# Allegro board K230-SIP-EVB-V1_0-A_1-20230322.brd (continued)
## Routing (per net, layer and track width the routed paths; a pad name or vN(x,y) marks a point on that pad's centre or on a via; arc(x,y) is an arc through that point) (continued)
QSPI0_CS0: length 42
  TOP w0.076: U19.E2 33.69,84.24 34.01,84.56 34.29,84.56 34.49,84.76 34.49,85.09
  TOP w0.127: 34.49,85.09 34.49,86.66 35.62,87.79 35.62,89.73 36.32,90.42 36.32,91.95 35.69,92.58 35.69,96.27 37.08,97.66 37.08,101.73 39.88,104.52 43.43,104.52 44.07,105.16 44.07,109.6 43.81,109.86 38.35,109.86 v1(37.72,110.49) U37.1
  BOTTOM w0.127: R212.2 v1(37.72,110.49)
QSPI0_D0: length 28.4
  TOP w0.076: 33.84,85.09 33.84,84.77 33.66,84.58 33.4,84.58 33.05,84.24 U19.F2
  TOP w0.127: U37.5 41.66,106.68 41.53,106.55 41.53,105.16 41.27,104.9 39.62,104.9 36.74,102.02 36.74,97.72 35.03,96 35.03,87.96 33.84,86.78 33.84,85.09
QSPI0_D1: length 29
  TOP w0.127: U19.F1 32.87,87.18 33.68,87.99 33.68,96.53 35.43,98.29 35.43,103.12 38.48,106.17 38.48,109.09 38.35,109.22 U37.2
QSPI0_D2: length 28.8
  TOP w0.127: U19.G1 32.22,88.08 33.06,88.93 33.06,97.07 34.04,98.04 34.04,99.11 34.37,99.44 34.37,102.69 36.35,104.68 36.35,104.89 35.93,105.31 35.93,105.52 36.07,105.67 36.28,105.67 36.71,105.25 36.92,105.25 37.97,106.3 37.97,107.82 37.85,107.95 U37.3
QSPI0_D3: length 30.3
  TOP w0.076: U19.G2 32.42,84.24 32.75,84.57 33.05,84.57 33.19,84.71 33.19,85.09
  TOP w0.127: U37.7 41.53,109.22 41.27,108.97 41.27,108.46 35.71,102.9 35.71,98.16 34,96.44 34,87.85 33.19,87.05 33.19,85.09
RMICN: length 65.3
  TOP w0.076: 36.25,83.91 35.79,83.91 U19.B3
  TOP w0.127: v1(59.82,117.73) 59.82,117.22 54.56,111.96 54.56,104.22 48.85,98.51 44.15,98.51 41.57,95.92 41.57,93.43 39.48,91.34 39.48,88.27 37.1,85.88 37.1,84.57 36.44,83.91 36.25,83.91 ; C285.1 v1(67.31,131.57)
  ART03 w0.127: v1(59.82,117.73) 60.33,118.24 60.33,119.51 67.31,126.49 v1(67.31,131.57)
RMICP: length 65.4
  TOP w0.127: C287.1 68.58,131.7 v1(68.45,131.57) ; v1(60.96,117.73) 54.86,111.63 54.86,104.01 49,98.15 44.3,98.15 41.91,95.76 41.91,93.36 39.76,91.21 39.76,88.14 37.35,85.74 37.35,84.42 36.52,83.59 U19.A3
  ART03 w0.127: v1(68.45,131.57) 68.45,125.22 v1(60.96,117.73)
RTC_1V8: length 139.7
  TOP w0.254: U19.D11 v3(34.49,78.06) U19.D12
  TOP w0.381: v1(76.2,64.01) 76.2,77.47 74.38,79.29 57.95,79.29 v1(57.02,78.36) 57.02,76.45 56.64,76.07 Y4.4 ; 70.87,38.1 70.87,35.94 71.36,35.44 72.52,35.44
  ART03 w0.381: v3(34.49,78.06) 48.94,78.06 49.4,77.6 50.08,77.6 50.55,78.06 56.72,78.06 v1(57.02,78.36) ; v1(76.2,64.01) 78.11,62.1 78.11,44.7 74.93,41.53 v1(74.93,40.13)
  ART03 w0.508: 57.78,1.91 60.33,1.91 61.59,3.17 64.14,3.17 65.41,1.91 66.67,3.17 66.67,19.43 73.79,26.54
  BOTTOM w0.305: v3(34.49,78.06) 34.54,78.11 C229.1 C230.1
  BOTTOM w0.381: R202.2 57.78,7.87 56.52,6.6 56.52,3.17 57.78,1.91
  vias: v1(74.93,38.86)
RTC_CLK_IN: length 16.6
  TOP w0.076: 34.49,74.93 34.49,75.46 U19.D15
  TOP w0.127: 34.49,74.93 34.49,74.73 36.2,73.03 48.51,73.03 R107.2
RTC_CLK_OUT: length 16.3
  TOP w0.127: U19.D16 34.17,74.54 36.2,72.52 R106.1
RTC_INT0: length 102.7
  TOP w0.127: U19.C16 34.82,74.8 35.96,73.66 46.48,73.66 v1(47.62,74.8)
  ART03 w0.127: v1(47.62,74.8) 48.77,73.66 58.29,73.66 58.93,74.3 64.48,74.3 68.83,69.94 68.83,64.64 72.14,61.34 72.14,57.53 72.64,57.02 72.64,55.5 71.88,54.74 71.88,44.2 71.25,43.56 71.25,27.18 v1(67.44,23.37)
  BOTTOM w0.127: 66.67,10.03 67.06,10.41 TVS8.1 67.94,22.86 v1(67.44,23.37)
RTC_INT1: length 102.5
  TOP w0.127: U19.D14 v3(34.49,76.11)
  ART03 w0.127: v3(34.49,76.11) 34.49,75.62 36.83,73.28 58.55,73.28 59.23,73.96 64.34,73.96 66.8,71.5 66.8,65.66 71.5,60.96 71.5,44.45 70.81,43.76 70.81,28.01 v1(66.17,23.37)
  BOTTOM w0.127: 64.14,10.03 64.52,10.41 TVS9.1 65.41,22.61 v1(66.17,23.37)
RTC_INT2: length 173.3
  TOP w0.127: v1(63.5,10.79) 63.5,9.4 60.07,5.97 44.07,5.97 41.78,8.26 6.35,8.26 4.06,10.54 4.06,13.72 J32.4 ; U19.E14 v3(33.84,76.11)
  ART03 w0.127: v3(33.84,76.11) 34.19,75.76 34.19,75.41 36.7,72.9 58.67,72.9 59.46,73.69 64.21,73.69 66.42,71.48 66.42,64.52 68.9,62.04 68.9,60.01 71.12,57.78 71.12,44.58 70.48,43.94 70.48,28.83 63.5,21.84 v1(63.5,10.79)
  BOTTOM w0.127: 61.59,10.03 61.98,10.41 TVS10.1 63.25,10.79 v1(63.5,10.79)
RTC_INT4: length 158.6
  TOP w0.127: U19.F14 v3(33.19,76.11) ; v1(60.96,10.79) 60.96,7.75 59.69,6.48 44.2,6.48 42.04,8.64 13.59,8.64 J33.2
  ART03 w0.102: 33.52,75.07 33.52,75.79 v3(33.19,76.11)
  ART03 w0.127: v1(60.96,10.79) 63.12,12.95 63.12,21.97 70.1,28.96 70.1,44.07 70.74,44.7 70.74,57.66 68.58,59.82 68.58,61.85 66.04,64.39 66.04,71.37 64.01,73.41 59.69,73.41 58.8,72.52 35.8,72.52 33.52,74.8 33.52,75.07
  BOTTOM w0.127: v1(60.96,10.79) 60.71,10.79 TVS11.1 59.44,10.41 59.05,10.03
RTC_OUT0: length 117
  TOP w0.127: U19.F13 v3(33.19,76.76)
  ART03 w0.102: 35.62,77.09 33.52,77.09 v3(33.19,76.76)
  ART03 w0.127: 35.62,77.09 35.87,76.83 48.13,76.83 49,75.97 62.13,75.97 62.61,76.45 63.96,76.45 70.23,70.18 70.23,65.53 73.79,61.98 73.79,59.94 74.3,59.44 74.3,49.4 73.66,48.77 73.66,42.04 72.64,41.02 72.64,27.3 66.67,21.34 v1(64.9,21.34)
  BOTTOM w0.127: 55.24,10.03 55.63,10.41 TVS12.1 ; 57.78,10.03 57.4,10.41 TVS12.1 ; TVS12.1 56.52,10.92 56.9,11.3 62.61,11.3 64.14,12.83 64.14,20.57 v1(64.9,21.34)
RTC_OUT1: length 61
  TOP w0.127: U19.E13 v3(33.84,76.76)
  ART03 w0.102: 34.82,75.93 34.82,76.31 34.69,76.44 34.17,76.44 v3(33.84,76.76)
  ART03 w0.127: 34.82,75.93 35.43,75.31 47.88,75.31 48.9,74.3 56.26,74.3 56.64,74.68 64.52,74.68 69.13,70.07 69.13,64.86 72.64,61.34 72.64,57.66 73.15,57.15 73.15,53.98 73.66,53.47 v1(73.66,51.44)
  BOTTOM w0.127: R92.1 v1(73.66,51.44)
SD2_CLK: length 61.3
  TOP w0.127: U19.P11 v3(27.99,78.06)
  ART03 w0.127: v1(25.05,97.28) 26.92,95.41 26.92,91.85 26.78,91.7 26.44,91.7 26.29,91.55 26.29,91.34 26.44,91.2 26.78,91.2 26.92,91.05 26.92,90.84 26.78,90.69 26.44,90.69 26.29,90.54 26.29,90.33 26.44,90.18 26.78,90.18 26.92,90.03 26.92,89.82 26.78,89.67 26.44,89.67 26.29,89.52 26.29,89.31 26.44,89.16 26.78,89.16 26.92,89.01 26.92,87.76 25.65,86.49 25.65,79.76 27.35,78.06 v3(27.99,78.06)
  BOTTOM w0.127: v1(25.05,97.28) 21.44,97.28 17.4,101.33 17.4,114.43 14.99,116.84 14.99,118.36 14.73,118.62 R156.2 U24.3 14.86,120.97 14.99,121.09 14.99,123.7 15.6,124.31 U23.5
SD2_CMD: length 60.3
  TOP w0.127: U19.P10 v3(27.34,78.71)
  ART03 w0.127: v3(27.34,78.71) 26.16,79.89 26.16,80.42 26.31,80.57 26.65,80.57 26.8,80.72 26.8,80.93 26.65,81.08 26.31,81.08 26.16,81.22 26.16,86.11 27.65,87.59 27.65,96.05 27.29,96.4 27.08,96.4 26.98,96.3 26.77,96.3 26.62,96.45 26.62,96.66 26.72,96.76 26.72,96.97 26.58,97.12 26.37,97.12 26.26,97.02 26.05,97.02 25.9,97.16 25.9,97.37 26.01,97.48 26.01,97.69 25.4,98.3 v1(25.05,98.3)
  BOTTOM w0.127: U23.3 17.8,124.35 17.53,124.08 16.13,124.08 15.49,123.44 15.49,121.16 15.68,120.97 U24.2 R157.2 16.89,118.62 17.14,118.36 17.14,115.95 17.91,115.19 17.91,101.54 21.15,98.3 v1(25.05,98.3)
SD2_DATA0: length 61.6
  TOP w0.102: U19.R16 26.69,74.81 v3(25.8,74.81)
  ART03 w0.127: v1(25.05,94.23) 24.13,93.31 24.13,84.84 23.62,84.33 23.62,79.88 24.89,78.61 24.89,75.82 25.8,74.91 v3(25.8,74.81)
  BOTTOM w0.127: v1(25.05,94.23) 23.77,94.23 16.89,101.12 16.89,113.16 13.21,116.84 13.21,118.36 12.95,118.62 R161.2 U26.2 11.75,120.97 11.56,121.16 11.56,123.32 12.45,124.21 13.08,124.21 13.4,124.53 U23.7
SD2_DATA1: length 62.2
  TOP w0.102: U19.R15 26.69,75.46 v3(25.8,75.46)
  ART03 w0.127: v1(25.05,93.22) 24.51,92.68 24.51,84.2 24.13,83.82 24.13,79.83 25.15,78.81 25.15,76.12 v3(25.8,75.46)
  BOTTOM w0.127: v1(25.05,93.22) 24.25,93.22 16.51,100.96 16.51,112.9 13.34,116.08 11.3,116.08 10.54,116.84 10.54,118.36 10.79,118.62 R160.2 11.18,119.38 10.29,120.27 10.29,120.97 10.99,120.97 11.18,121.16 11.18,123.44 12.3,124.57 U23.8
SD2_DATA2: length 60.2
  TOP w0.102: v3(25.8,76.11) 26.69,76.11 U19.R14
  ART03 w0.127: v3(25.8,76.11) 25.53,76.39 25.53,78.83 24.89,79.46 24.89,87.12 25.4,87.63 25.4,88.9 24.89,89.41 24.89,92.33 25.65,93.09 25.65,94.65 v1(25.05,95.25)
  BOTTOM w0.127: U23.1 20,124.65 19.3,123.95 19.3,121.09 19.43,120.97 U25.2 R159.2 19.56,118.75 18.96,118.15 18.96,102.45 20.76,100.65 25.21,100.65 26.29,99.57 26.29,96.49 v1(25.05,95.25)
SD2_DATA3: length 60.2
  TOP w0.127: U19.R13 v3(27.34,77.41)
  ART03 w0.127: v3(27.34,77.41) 25.18,79.58 25.18,86.77 25.78,87.38 25.78,89.53 25.63,89.68 25.42,89.68 25.27,89.82 25.27,90.03 25.42,90.18 25.63,90.18 25.78,90.33 25.78,90.54 25.63,90.69 25.42,90.69 25.27,90.84 25.27,91.05 25.42,91.2 25.63,91.2 25.78,91.35 25.78,91.56 25.63,91.71 25.42,91.71 25.27,91.86 25.27,92.07 25.42,92.22 26.29,92.22 26.42,92.34 26.42,95.12 25.27,96.27 v1(25.05,96.27)
  BOTTOM w0.127: U23.2 18.9,121.26 18.61,120.97 U25.3 R158.2 18.41,118.62 18.67,118.36 18.67,102.2 20.69,100.19 25.03,100.19 25.78,99.44 25.78,97 v1(25.05,96.27)
SD2_DET: length 72.8
  TOP w0.127: J34.2 1.52,64.52 1.52,87.63 v1(1.91,88.01) ; v1(13.21,127) TVS4.1 13.21,128.65 R155.2
  BOTTOM w0.127: v1(13.21,127) 11.81,127 11.2,126.39 U23.9 11.2,124.23 10.67,123.7 9.65,123.7 9.4,123.44 9.4,119.76 7.75,118.11 7.75,111.89 1.4,105.54 1.4,88.52 v1(1.91,88.01)
SDIO_CLK: length 41.7
  TOP w0.076: 36.32,76.76 35.79,76.76 U19.B14
  TOP w0.127: v1(44.96,80.52) 45.21,80.26 45.21,78.49 43.69,76.96 37.03,76.96 36.83,76.76 36.32,76.76 ; U41.5 60.81,86.09 60.64,85.92 U38.3 v1(59.69,85.22)
  ART03 w0.127: v1(44.96,80.52) 45.59,81.15 45.59,83.31 50.89,88.61 57.57,88.61 59.69,86.49 v1(59.69,85.22)
  BOTTOM w0.127: R274.2 v1(59.69,85.22)
SDIO_CMD: length 43.7
  TOP w0.127: v1(46.1,80.52) 46.1,78.61 43.92,76.44 U19.A14 ; v1(57.53,87.5) U38.2 60.64,86.8 60.83,86.61 63.37,86.61 64.01,87.25 64.01,87.88 64.41,88.29 U41.3
  ART03 w0.127: v1(57.53,87.5) 50.62,87.5 49.49,86.38 49.49,86.17 49.82,85.84 49.82,85.63 49.67,85.48 49.46,85.48 49.14,85.81 48.92,85.81 48.78,85.66 48.78,85.45 49.1,85.12 49.1,84.91 48.95,84.76 48.74,84.76 48.42,85.09 48.21,85.09 46.1,82.98 v1(46.1,80.52)
  BOTTOM w0.127: R273.2 v1(57.53,87.5)
SDIO_DAT0: length 43.3
  TOP w0.127: v1(58.67,80.77) 60.64,82.74 U40.2 60.64,83.76 60.77,83.89 U41.7 ; v1(43.94,78.99) 42.81,77.86 36.59,77.86 36.46,77.74 U19.A12
  ART03 w0.127: v1(58.67,80.77) 58.29,80.39 56.64,80.39 55.88,79.63 51.05,79.63 50.9,79.78 50.9,80.24 50.75,80.39 49.52,80.39 49.37,80.24 49.37,79.65 49.22,79.5 48.93,79.5 48.78,79.65 48.78,81.26 48.63,81.41 48.42,81.41 48.27,81.26 48.27,79.78 48.12,79.63 47.91,79.63 47.76,79.78 47.76,81.26 47.61,81.41 47.4,81.41 47.25,81.26 47.25,80.02 46.23,78.99 v1(43.94,78.99)
  BOTTOM w0.127: R278.2 58.67,81.15 v1(58.67,80.77)
SDIO_DAT1: length 40.9
  TOP w0.127: U19.A10 40.3,79.04 41.01,79.74 42.15,79.74 v1(42.93,80.52) ; v1(59.69,80.77) U40.3 60.64,81.6 60.96,81.92 63.37,81.92 64.24,82.79 U41.8
  ART03 w0.127: v1(59.69,80.77) 59.05,81.41 58.34,81.41 57.71,80.77 56.52,80.77 55.75,80.01 51.54,80.01 51.39,80.16 51.39,81.89 51.24,82.04 51.03,82.04 50.88,81.89 50.88,80.9 50.75,80.77 50.5,80.77 50.37,80.9 50.37,81.64 50.22,81.79 50.01,81.79 49.86,81.64 49.86,80.9 49.74,80.77 49.48,80.77 49.35,80.9 49.35,81.77 49.21,81.92 46.74,81.92 46.61,81.79 46.61,80.14 46.23,79.76 43.69,79.76 v1(42.93,80.52)
  BOTTOM w0.127: R276.2 v1(59.69,80.77)
SDIO_DAT2: length 44.3
  TOP w0.127: U41.1 64.33,90.49 63.75,91.06 60.77,91.06 60.64,91.19 U39.2 v1(57.4,91.95) ; v1(42.93,78.97) 42.13,78.17 36.33,78.17 U19.A11
  ART03 w0.127: v1(57.4,91.95) 51.94,91.95 43.97,83.98 43.97,83.77 44.27,83.47 44.27,83.26 44.12,83.11 43.91,83.11 43.61,83.41 43.4,83.41 43.25,83.26 43.25,83.05 43.55,82.75 43.55,82.54 43.4,82.39 43.19,82.39 42.89,82.69 42.68,82.69 42.42,82.42 42.42,79.48 v1(42.93,78.97)
  BOTTOM w0.127: R277.2 v1(57.4,91.95)
SDIO_DAT3: length 43.3
  TOP w0.127: v1(43.94,80.52) 44.58,79.88 44.58,78.74 43.31,77.47 36.83,77.47 36.45,77.09 U19.A13 ; U41.2 64.54,89.39 63.25,90.68 60.83,90.68 60.64,90.49 U39.3 57.53,89.66 v1(57.4,89.79)
  ART03 w0.127: v1(43.94,80.52) 44.96,81.53 44.96,83.44 51.31,89.79 53.61,89.79 53.76,89.94 53.76,90.28 53.9,90.42 54.11,90.42 54.26,90.28 54.26,89.94 54.41,89.79 v1(57.4,89.79)
  BOTTOM w0.127: v1(57.4,89.79) 57.53,89.66 R275.2
SDIO_DET: length 89.6
  TOP w0.127: U41.9 66.65,81.69 v1(66.67,81.66)
  ART03 w0.127: v1(66.67,81.66) 58.42,89.92 58.42,91.82 51.69,98.55 v1(34.92,98.55)
  BOTTOM w0.127: v1(66.67,81.66) TVS15.1 68.83,81.66 R279.2 ; J34.15 8.89,81.28 13.08,77.09 14.48,77.09 15.24,77.85 15.24,87 20.45,92.2 28.57,92.2 v1(34.92,98.55)
SYS_ON_OFF: length 40.1
  TOP w0.305: K2.1 73.53,27.07 C293.1
  ART03 w0.127: 67.94,1.91 69.34,3.3 69.34,18.67 73.82,23.15 K2.1
SYS_SW: length 47.2
  TOP w0.127: K3.2 C294.2 73.53,36.83 73.15,36.45 v1(71.75,36.45)
  ART03 w0.127: v1(64.9,22.35) 67.18,22.35 72.26,27.43 72.26,35.94 v1(71.75,36.45)
  BOTTOM w0.127: 52.7,10.03 53.09,10.41 TVS13.1 55.24,11.68 62.36,11.68 63.37,12.7 63.37,20.83 v1(64.9,22.35)
UART0_RXD: length 74.1
  TOP w0.127: v1(40.01,110.49) 41.53,112.01 47.24,112.01 48.46,110.8 U35.4
  ART03 w0.127: v1(40.01,110.49) 40.01,110.11 38.86,108.97 29.59,108.97 20.83,100.2 20.83,93.22 18.03,90.42 v1(18.03,88.9)
  BOTTOM w0.127: J34.16 3.81,80.01 9.65,80.01 13.08,76.58 14.61,76.58 15.62,77.6 15.62,86.49 v1(18.03,88.9)
UART0_RXD_3V3: length 24.7
  TOP w0.127: U35.11 48.46,107.24 49.91,105.79 v1(50.29,105.79) ; R189.2 62.87,100.58 62.87,100.33 J28.1
  BOTTOM w0.127: J28.1 61.85,101.35 59.94,101.35 55.5,105.79 v1(50.29,105.79)
UART0_TXD: length 76.6
  TOP w0.127: U35.3 48.86,110.91 47.37,112.39 40.64,112.39 v1(40.01,111.76)
  ART03 w0.127: v1(13.46,74.68) 16.13,77.34 16.13,81.53 18.67,84.07 18.67,90.65 21.21,93.19 21.21,100.08 29.46,108.33 38.99,108.33 40.64,109.98 40.64,111.12 v1(40.01,111.76)
  BOTTOM w0.127: J34.10 3.81,74.93 6.1,74.93 6.73,74.3 13.08,74.3 v1(13.46,74.68)
UART0_TXD_3V3: length 28
  TOP w0.127: v1(52.7,106.3) 50.04,106.3 48.86,107.48 U35.12 ; R190.2 64.64,101.09 J28.2
  BOTTOM w0.127: v1(52.7,106.3) 55.71,106.3 60.15,101.85 63.88,101.85 J28.2
UART4_RXD: length 15.6
  TOP w0.127: U35.6 47.66,110.45 47.5,110.62 v1(45.59,110.62)
  BOTTOM w0.127: v1(45.59,110.62) 45.59,109.6 37.59,101.6 R219.2
UART4_RXD_3V3: length 136.8
  TOP w0.127: R191.2 v1(60.07,100.2) ; v1(46.61,107.57) 47.24,107.57 47.66,107.99 U35.9
  ART03 w0.127: v1(46.61,107.57) 29.21,107.57 21.59,99.95 21.59,93.09 19.05,90.55 19.05,83.95 16.51,81.41 16.51,73.44 11.05,67.98 11.05,62.48 6.07,57.5 6.07,53.95 4.83,52.7 4.83,29.56 5.71,28.67 5.71,23.5 J32.2
  BOTTOM w0.127: v1(46.61,107.57) 46.11,107.07 46.11,106.35 47.94,104.52 55.29,104.52 59.61,100.2 v1(60.07,100.2)
UART4_TXD: length 20.4
  TOP w0.127: v1(42.16,111.51) 47.24,111.51 48.06,110.69 U35.5
  BOTTOM w0.127: R218.2 36.45,101.36 40.64,105.55 40.64,111 41.15,111.51 v1(42.16,111.51)
UART4_TXD_3V3: length 139.1
  TOP w0.127: R192.2 v1(61.21,100.2) ; U35.10 48.06,107.37 47.24,106.55 v1(46.61,106.55)
  ART03 w0.127: J32.3 6.1,21.34 6.1,28.83 5.21,29.72 5.21,52.45 6.35,53.59 6.35,57.02 11.43,62.1 11.43,67.82 17.02,73.41 17.02,81.28 21.96,86.22 21.96,99.81 28.32,106.17 46.23,106.17 v1(46.61,106.55)
  BOTTOM w0.127: v1(46.61,106.55) 48.13,105.03 55.5,105.03 59.69,100.84 60.58,100.84 v1(61.21,100.2)
USB0_OTG_DN: length 50.4
  TOP w0.14: J11.B7 71.62,72.53 71.37,72.77 71.37,73.28 71.62,73.53 ; v1(47.88,82.8) 47.88,83.05 47.74,83.19 43.18,83.19 42.46,82.47 40.91,82.47 39.18,80.74 39.18,80.55 39.01,80.39 38.78,80.39 38.62,80.55 38.62,80.74 38.45,80.9 37.85,80.9 37.27,80.32 36.13,80.32 U19.A8 ; 71.62,73.53 J11.A7 ; 71.62,73.53 71.49,73.66 70.61,73.66 v1(70.36,73.41)
  ART03 w0.14: v1(70.36,73.41) 70.36,73.65 70.22,73.79 69.72,73.79 69.39,74.12 69.39,75.81 67.35,77.84 67.35,78.82 64.35,81.83 62.82,81.83 61.72,82.93 48.01,82.93 v1(47.88,82.8)
  BOTTOM w0.14: U29.2 67.37,73.61 67.51,73.75 70.02,73.75 v1(70.36,73.41)
USB0_OTG_DP: length 51.1
  TOP w0.102: 36.3,80.66 35.79,80.66 U19.B8
  TOP w0.14: 36.3,80.66 37.13,80.66 37.71,81.24 39.2,81.24 40.77,82.8 42.32,82.8 43.04,83.52 47.58,83.52 v1(47.88,83.82) ; v1(70.36,74.42) 70.78,74 71.63,74 71.66,74.03 J11.B6 73.27,74.03 73.41,73.89 73.41,73.17 73.27,73.03 J11.A6
  ART03 w0.14: v1(70.36,74.42) 70.06,74.12 69.86,74.12 69.72,74.26 69.72,75.95 67.69,77.98 67.69,78.96 64.49,82.17 62.96,82.17 61.86,83.27 48.43,83.27 v1(47.88,83.82)
  BOTTOM w0.14: v1(70.36,74.42) 70.02,74.08 67.51,74.08 67.37,74.22 U29.3
USB0_OTG_ID: length 83.1
  TOP w0.127: v1(47.12,78.99) 47.12,80.39 46.23,81.28 42.8,81.28 42.55,81.03 41.4,81.03 39.75,79.38 36.43,79.38 U19.A9 ; 71.12,45.85 72.39,45.85 73.79,47.24 v1(77.09,47.24) ; J11.B5 73.18,75.03 74.04,74.17 74.04,72.64 73.43,72.03 J11.A5 71.53,72.03 v1(71.06,71.56)
  ART03 w0.127: v1(47.12,78.99) 49.91,78.99 50.16,78.74 50.41,78.74 50.92,79.25 62.61,79.25 70.3,71.56 v1(71.06,71.56) 71.98,70.64 71.98,65.3 75.56,61.72 75.56,52.07 77.09,50.55 v1(77.09,47.24)
  BOTTOM w0.127: TVS6.1 70.75,71.25 v1(71.06,71.56)
USB0_OTG_VBUS: length 1.8
  BOTTOM w0.381: U29.4 70.42,76.2 v1(70.61,76.2)
VAA_DDR: length 9.1
  TOP w0.254: U19.H12 v3(31.89,77.41)
  BOTTOM w0.305: v3(31.89,77.41) 32.13,77.17 C217.1 32.13,76.58 32.32,76.39 32.32,74.99 32.77,74.55 32.77,71.25 33.53,70.48 34.54,70.48
  vias: v1(31.75,40.64) v1(31.75,39.62) v1(33.53,58.55) v1(34.54,58.55)
VCM: length 4.8
  TOP w0.254: U19.B4 v3(35.79,83.26)
  BOTTOM w0.254: C235.1 35.94,83.57 36.2,83.82 37.9,83.82
  BOTTOM w0.381: C236.1 38.99,83.82 37.9,83.82
VPWM_CORE: length 86.1
  TOP w0.254: v1(4.32,27.44) 5.09,26.67 30.73,26.67 33.15,24.26 R33.2
  ART03 w0.254: v1(4.32,27.44) 3.68,28.07 3.68,51.24 1.09,53.83 1.09,68.91 2.03,69.85 3.81,69.85 J34.7
VPWM_KPU: length 105.1
  TOP w0.254: v1(4.32,26.16) 30.48,26.16 32.89,23.75 36.7,23.75 40.01,20.45 58.29,20.45 R21.2
  ART03 w0.254: v1(4.32,26.16) 4.95,26.8 4.95,27.81 4.09,28.68 4.09,51.41 1.5,54 1.5,66.78 2.03,67.31 3.81,67.31 J34.5
VSYNC0: length 135.3
  TOP w0.127: v1(45.76,131.57) J21.53
  ART03 w0.127: J34.13 10.54,84.2 10.54,89.41 12.55,91.41 12.55,97.64 13.84,98.93 13.84,101.22 26.67,114.05 36.58,114.05 39.88,117.35 39.88,122.17 39.15,122.9 39.15,130.59 41.02,132.46 43.56,132.46 44.07,131.95 45.38,131.95 v1(45.76,131.57) 45.76,127.73 53.34,120.14 53.34,104.9 50.55,102.11 49.78,102.11 v1(49.28,102.62)
  BOTTOM w0.127: R230.2 43.94,88.52 49.28,93.85 v1(49.28,102.62)
N22177941: length 2.1
  TOP w0.254: U3.9 R9.1
N22182672: length 2
  TOP w0.305: 60.83,21.97 60.83,24
N22185023: length 2.4
  TOP w0.305: U1.1 LED1.2
N22185059: length 2.1
  TOP w0.305: U1.5 R2.1
N22185516: length 0.8
  TOP w0.305: R51.1 21.84,36.96
N22185553: length 3.4
  TOP w0.305: U10.2 21.72,34.54 21.08,35.18 R51.2 R52.2
N22186056: length 0.8
  TOP w0.305: R54.1 28.7,36.83
N22186079: length 4.4
  TOP w0.305: U11.4 27.93,30.75 27.94,30.73 R53.1 C109.1 R231.2
N22186091: length 3.2
  TOP w0.305: U11.2 28.57,34.54 27.94,35.18 R54.2 R55.1
N22187793: length 3.4
  TOP w0.305: U12.2 30.48,49.15 29.84,49.78 R58.2 R59.1
N22191614: length 4.4
  TOP w0.305: U13.4 22.34,46.47 v1(21.46,45.59) C126.1 R63.1
  BOTTOM w0.305: R64.2 21.97,45.09 v1(21.46,45.59)
N22191677: length 3.2
  TOP w0.305: R65.1 R62.2 22.35,49.78 22.99,49.15 U13.2
N22192931: length 0.6
  TOP w0.305: R67.2 14.99,29.21
N22192964: length 3.2
  TOP w0.305: R69.1 R68.2 14.22,35.18 14.86,34.54 U14.2
N22212532: length 5.1
  TOP w0.254: U4.6 58.42,27.06 59.18,26.29 R13.2 R16.1 R20.1
N22217230: length 2.1
  TOP w0.254: U5.9 R24.1
N22249226: length 4.2
  TOP w0.305: v1(58.29,63.75) 58.04,64.01 U17.2
  BOTTOM w0.305: v1(58.29,63.75) 58.55,64.01 R82.1 R81.2
N22250085: length 2.5
  TOP w0.305: U16.3 35.88,28.01 35.05,27.18 C146.1
N22250107: length 3.4
  TOP w0.305: R78.1 R77.2 35.05,33.02 35.23,32.84 U16.7
N22292047: length 3.9
  TOP w0.127: R122.2 2.54,32.38
N22293444: length 1.4
  TOP w0.127: U19.C13 v3(35.14,76.76)
  BOTTOM w0.127: R91.1 35.45,76.45 v3(35.14,76.76)
N22293459: length 2.6
  TOP w0.127: SW1.4 v1(77.47,63.63)
  BOTTOM w0.127: R104.1 v1(77.47,63.63)
N22293460: length 2.6
  TOP w0.127: SW1.3 v1(74.93,63.63)
  BOTTOM w0.127: R103.1 v1(74.93,63.63)
N22293491: length 4.1
  TOP w0.127: Y1.3 50.5,83.31 49.4,83.31 R97.1
N22293492: length 2.4
  TOP w0.254: Y1.1 55.66,86.65 56.13,87.12 R96.1
N22305390: length 17.1
  TOP w0.127: R121.1 13.21,77.47 14.42,76.26 22.41,76.26 24.54,78.39 U19.T11
N22305392: length 17.2
  TOP w0.127: R120.1 12.83,76.2 13.84,75.18 22.73,75.18 25.28,77.74 U19.T12
N22305394: length 17.2
  TOP w0.102: 25.64,76.44 U19.T14
  TOP w0.127: 25.64,76.44 25.25,76.44 22.91,74.09 15.04,74.09 14.22,73.28 11.05,73.28 R119.1
N22305396: length 17.1
  TOP w0.102: 25.65,75.79 U19.T15
  TOP w0.127: 25.65,75.79 25.04,75.79 22.41,73.15 14.73,73.15 13.97,72.39 R118.1
N22305398: length 18.2
  TOP w0.076: 26.16,78.71 26.69,78.71 U19.R11
  TOP w0.127: 26.16,78.71 24.48,78.71 22.48,76.71 14.61,76.71 12.57,78.74 R116.1
N22325333: length 10.6
  TOP w0.076: 36.32,80.01 35.79,80.01 U19.B9
  TOP w0.127: v1(44.45,81.92) 42.8,81.92 42.29,81.41 41.15,81.41 39.5,79.76 36.96,79.76 36.7,80.01 36.32,80.01
  BOTTOM w0.127: R138.2 v1(44.45,81.92)
N22325479: length 16.1
  TOP w0.076: 36.32,81.31 35.79,81.31 U19.B7
  TOP w0.127: 36.32,81.31 36.8,81.31 37.91,82.42 38.23,82.42
  TOP w0.305: 38.23,82.42 38.99,82.42 39.88,83.31 39.88,83.69 41.53,85.34 44.7,85.34 45.47,86.11 48.64,86.11 R137.2
N22328655: length 2.5
  TOP w0.127: U30.8 58.71,130.33 FB29.1
N22328657: length 2.5
  TOP w0.127: U30.5 60.67,130.33 FB30.1
N22328764: length 9.2
  TOP w0.127: J18.6 76.2,122.04 72.77,118.62 R168.2 R169.2 C282.1
N22328820: length 9
  TOP w0.127: J18.1 77.29,130.48 75.56,132.21 R165.2 C277.2 C276.2
N22328860: length 2.8
  TOP w0.127: R164.1 C275.2 C276.1
N22328921: length 10.3
  TOP w0.127: 64.14,117.98 65.53,117.98 65.91,118.36 65.91,119.51 67.18,120.78 70.74,120.78 71.2,121.23 J18.4
N22328923: length 8.7
  TOP w0.127: J18.3 71.5,128.39 69.6,126.49 C281.2
N22328925: length 5.3
  TOP w0.127: R166.2 68.45,130.3 69.2,129.56 J18.8
N22328935: length 9.7
  TOP w0.127: R167.2 66.67,119.51 67.44,120.27 72.64,120.27 73.3,120.92 J18.7
N22328937: length 1.1
  TOP w0.127: R167.1 C280.2
N22328939: length 1.1
  TOP w0.127: R166.1 C278.2
N22328989: length 2.5
  BOTTOM w0.127: FB31.1 60.67,130.33 U31.8
N22328991: length 2.5
  BOTTOM w0.127: FB32.1 58.71,130.33 U31.5
N22333182: length 25.4
  TOP w0.102: U19.P6 27.34,81.96 v3(27.34,82.61)
  ART03 w0.102: 27.91,84.3 27.67,84.06 27.67,82.94 v3(27.34,82.61)
  ART03 w0.127: 27.91,84.3 30.48,86.87 30.48,93.34 32.38,95.25 36.45,95.25 37.33,96.13 v1(37.33,96.65)
  BOTTOM w0.127: R140.2 38.73,98.06 v1(37.33,96.65)
N22333186: length 25.7
  TOP w0.127: U19.P5 v3(27.99,82.61)
  ART03 w0.102: 28.45,83.69 28.32,83.56 28.32,82.94 v3(27.99,82.61)
  ART03 w0.127: v1(38.32,95.63) 37.72,95.63 36.58,94.49 32.64,94.49 31.24,93.09 31.24,86.49 28.45,83.69
  BOTTOM w0.127: R139.2 41.02,98.59 38.32,95.89 v1(38.32,95.63)
N22367376: length 18.2
  TOP w0.076: 25.42,77.32 25.51,77.41 26.69,77.41 U19.R12
  TOP w0.127: 25.42,77.32 25.3,77.32 22.78,74.8 14.61,74.8 13.84,74.04 12.83,74.04 11.94,74.93 R115.1
N22368053: length 3
  TOP w0.127: U32.1 67.07,135.77 65.91,134.62 R172.1
N22368198: length 2.3
  TOP w0.127: U32.3 68.82,134.36 C287.2
N22368201: length 2.5
  TOP w0.127: C285.2 67.94,134.75 U32.2
N22445143: length 12.2
  TOP w0.305: v1(41.4,22.23) R32.1 ; R31.1 R29.1 C54.1 v1(43.31,27.3) 43.56,27.3 44.97,28.71 U6.1
  ART03 w0.305: v1(41.4,22.23) 43.31,24.13 v1(43.31,27.3)
N22445145: length 2.2
  TOP w0.254: C61.2 R33.1 R32.2
N22445207: length 4.4
  TOP w0.305: U6.2 45.47,28.45 43.31,26.29 R30.2
N22445414: length 0.8
  TOP w0.305: U6.6 45.97,31.62
N22458660: length 5.4
  TOP w0.305: R44.1 R41.1 C78.1 13.82,48.77 U8.1
N22458931: length 0.8
  TOP w0.305: U8.6 16.38,53.08
N22477210: length 5.4
  TOP w0.305: R48.2 R46.1 C89.1 63.25,64.77 64.65,66.18 U9.1
N22477358: length 0.8
  TOP w0.305: U9.6 65.65,69.08
N22537740: length 2.6
  TOP w0.305: 52.96,30.1 51.18,30.1 50.93,29.84 C27.2
N22537802: length 3
  TOP w0.254: U4.13 53.86,28.06 52.58,29.34 C27.1
N22537853: length 2.8
  TOP w0.254: R15.2 52.83,28.32 53.6,27.55 U4.14
N22538184: length 4.1
  TOP w0.254: R19.1 59.05,30.35 58.29,29.59 58.29,28.45 57.9,28.06 U4.8
N22538189: length 3.8
  TOP w0.254: U4.7 58.42,27.55 59.18,28.32 R18.1 C36.1
N22538194: length 4.6
  TOP w0.254: C37.1 58.67,31.37 56.63,29.33 U4.9
N22561506: length 5.4
  TOP w0.305: U7.1 26.16,19.91 C65.1 R36.1 R38.2
N22561654: length 0.8
  TOP w0.305: U7.6 21.85,22.47
N22646851: length 3.4
  TOP w0.127: J21.52 45.26,134.79 45.85,135.38 v2(46.03,135.38)
  BOTTOM w0.127: 47.12,134.49 46.23,135.38 v2(46.03,135.38)
N22647187: length 5.3
  TOP w0.127: J21.42 42.76,135.72 43.18,136.14 v2(44.07,136.14)
  BOTTOM w0.127: v2(44.07,136.14) 44.58,135.64 44.58,134.75 44.83,134.49
N22647219: length 5.4
  TOP w0.127: J21.44 43.26,135.05 43.24,135.07 v2(43.24,135.38)
  BOTTOM w0.127: v2(43.24,135.38) 42.86,135.76 41.02,135.76 40.26,135 40.26,134.49
N22647230: length 2.6
  TOP w0.127: J21.48 44.26,135.2 v2(44.07,135.38)
  BOTTOM w0.127: v2(44.07,135.38) 43.69,135 43.69,134.49
N22647232: length 2.9
  TOP w0.127: J21.50 44.76,135 v2(45.14,135.38)
  BOTTOM w0.127: v2(45.14,135.38) 45.14,135.33 45.97,134.49
N22647453: length 2.5
  TOP w0.127: J21.30 39.75,135.13 v2(39.88,135.25)
  BOTTOM w0.127: 39.12,134.49 v2(39.88,135.25)
N22675755: length 4.1
  TOP w0.305: R86.2 C158.1 R84.1 43.05,45.59 43.04,45.61 U18.4
N22675895: length 3.2
  TOP w0.305: U18.2 43.69,49.15 43.05,49.78 R85.2 R87.1
N22676270: length 4.1
  TOP w0.305: C138.1 39.5,50.8 38.48,50.8 37.97,50.28 U15.7
N22676291: length 2
  TOP w0.305: R73.1 37.47,44.96 U15.3
N22676313: length 3.9
  TOP w0.305: U15.8 37.47,50.93 R71.2 R72.1
N22682206: length 1
  TOP w0.305: 60.83,29.34 60.83,28.32
N22702416: length 3.9
  TOP w0.127: U20.1 41.35,116.01 C255.2 R224.1 R225.1
N22702442: length 1.8
  TOP w0.127: R132.2 36.96,115.7 37.27,116.01 U20.8
N22756394: length 2.4
  TOP w0.114: R187.2 63.91,112.17 63.91,111.85 64.23,111.53 U33.1
N22756396: length 2.4
  TOP w0.114: U33.2 63.23,111.53 63.56,111.86 63.56,112.2 R188.2
N22756731: length 3.4
  TOP w0.127: R189.1 62.61,102.36 62.61,103.76 62.23,104.14 U33.8
N22756757: length 3.3
  TOP w0.127: U33.9 63.23,102.38 R190.1
N22756876: length 9.7
  TOP w0.127: R191.1 58.67,103.5 58.67,108.58 60.23,110.14 U33.5
N22756879: length 3.6
  TOP w0.127: R192.1 60.23,103.09 U33.6
N22757084: length 2.3
  TOP w0.305: U33.10 64.23,104.36 v1(63.88,104.01)
  BOTTOM w0.305: v1(63.88,104.01) C289.2
N22757146: length 3.8
  TOP w0.127: v1(60.96,104.01) 61.23,104.28 U33.7
  BOTTOM w0.127: C290.2 v1(60.96,104.01) 60.96,104.78 60.83,104.9 R194.1
N22778016: length 6.5
  TOP w0.127: Y2.3 54.56,81.15 52.83,81.15 C243.1 51.69,81.03 51.44,81.03 R102.2 51.05,80.64 R105.1
N22778033: length 4.8
  TOP w0.127: Y2.1 53.09,81.53 52.7,81.53 C242.1 51.69,81.53 51.44,81.53 R102.1 51.05,81.92 R100.1
N22813541: length 4
  TOP w0.127: Y4.3 50.55,76.07 R108.1
N22813555: length 4.2
  TOP w0.127: Y3.1 53.58,71.77 52.83,72.52 C245.1 R106.2
N22813557: length 4.2
  TOP w0.127: R107.1 R109.2 C246.1 52.7,73.53 53.45,74.28 Y3.2
N22833174: length 3.9
  TOP w0.127: R227.1 R226.1 C259.2 50.87,116.01 U21.1
N22833184: length 2.1
  TOP w0.127: R136.2 46.43,116.01 U21.8
N22838956: length 2.7
  TOP w0.127: U21.9 47.66,114.84 47.5,114.68 45.85,114.68 R135.1
N22845324: length 3.1
  TOP w0.127: R204.1 C292.2 50.29,108.46 49.73,109.02 U35.1
N22845340: length 1.8
  TOP w0.127: U35.8 46.66,109.02 46.35,108.71 R195.2
N22848145: length 0.8
  TOP w0.305: R4.2 66.04,36.96
N22848155: length 2.2
  TOP w0.305: R5.2 65.28,30.73 65.26,30.75 U2.4
N22848169: length 3.5
  TOP w0.305: U2.2 65.91,34.54 65.28,35.18 R4.1 R6.1
N22850140: length 5.1
  BOTTOM w0.127: R198.2 64.14,5.71 J31.3
N22850142: length 5.1
  BOTTOM w0.127: R196.2 66.67,5.71 J31.1
N22850146: length 5.1
  BOTTOM w0.127: 62.87,4.45 61.59,5.71 R197.2
N22850259: length 5.6
  BOTTOM w0.127: 50.16,4.45 52.7,6.99 R201.2
N22850264: length 5.6
  BOTTOM w0.127: 52.7,4.45 55.24,6.99 R200.2
N22850508: length 3.9
  TOP w0.127: K3.1 R203.1
N22859730: length 4.1
  TOP w0.127: v3(30.11,74.18) 30.92,74.99 U19.J16
  BOTTOM w0.127: v3(30.11,74.18) 30.38,73.9 30.38,73.05 29.72,72.39 R94.1
N22859732: length 4.9
  TOP w0.127: v3(29.97,73.41) 31.57,75 U19.H16
  BOTTOM w0.127: v3(29.97,73.41) 29.97,73.28 29.63,72.94 28.49,72.94 R93.1
N22896944: length 1.9
  TOP w0.127: U21.3 48.86,118.46 R133.2
N22896964: length 2
  TOP w0.127: U21.4 48.46,118.42 R134.2
N22896985: length 2.3
  TOP w0.127: R131.2 38.14,117.57 U20.6
N22897005: length 1.9
  TOP w0.127: R130.2 38.54,118.44 U20.5
N22897025: length 1.9
  TOP w0.127: U20.4 38.94,118.44 R129.2
N22897045: length 2.3
  TOP w0.127: R128.2 39.34,117.57 U20.3
N22994425: length 5.1
  BOTTOM w0.127: R199.2 59.05,5.71 57.78,4.45
N23005611: length 2.8
  TOP w0.127: FB29.2 C296.1 J19.1
N23005650: length 2.8
  TOP w0.127: J19.2 C295.1 FB30.2
N23005853: length 2.8
  BOTTOM w0.127: J20.1 C297.1 FB31.2
N23005873: length 2.8
  BOTTOM w0.127: FB32.2 C298.1 J20.2
N23088396: length 5.9
  BOTTOM w0.254: R209.2 14.61,109.41 Q1.2 ; R209.2 13.59,109.98 13.08,110.49 U36.2 ; R209.2 R208.1
N23088453: length 3.2
  BOTTOM w0.127: Q1.3 15.75,105.03 R210.2
N23088513: length 2.3
  BOTTOM w0.254: R211.2 8.4,109.84 U36.4
N23103726: length 6.7
  TOP w0.305: U27.4 R162.2 70.74,55.12 70.99,54.86 70.99,51.82 Q2.3
N23103803: length 3.6
  TOP w0.127: R221.2 R220.2 69.54,47.18 Q2.1
N23147657: length 5.2
  TOP w0.381: Q4.1 52.39,128.08 R267.1 R265.2
N23147659: length 2.8
  TOP w0.381: R266.1 R263.1 Q4.3
N23147737: length 2.6
  TOP w0.305: R263.2 53.34,130.62 Q5.1
N23166270: length 2.3
  TOP w0.127: U3.5 66.42,47.62 R268.2
N23166302: length 2.6
  TOP w0.127: U3.6 65.78,48.13 R269.2
N23166482: length 4.6
  TOP w0.127: R270.2 55.88,46.35 55.88,48.26 55.5,48.64 U5.5
N23166503: length 5.4
  TOP w0.127: U5.6 55.71,49.14 56.64,48.21 R271.2
N23178807: length 2.9
  TOP w0.127: U30.4 60.67,121.45 C307.2
N23178824: length 2.9
  TOP w0.127: U30.3 60.02,121.48 C308.2
N23178875: length 3.1
  BOTTOM w0.127: U31.4 58.71,122.77 58.93,122.56 58.93,121.67 C309.2
N23178892: length 2.9
  BOTTOM w0.127: C310.2 59.36,121.48 U31.3
N222777460: length 5.1
  TOP w0.305: U27.3 70.17,58.74 68.96,57.53 R163.1
N228657051: length 1.4
  TOP w0.305: R3.2 LED2.1
N228906461: length 24.5
  TOP w0.127: U19.K3 v3(29.94,83.91)
  ART03 w0.127: v1(38.23,94.58) 37.17,94.58 36.7,94.11 32.77,94.11 31.62,92.96 31.62,85.59 v3(29.94,83.91)
  BOTTOM w0.127: v1(38.23,94.58) 38.39,94.58 38.86,95.05 38.86,95.9 42.16,99.2 R127.2

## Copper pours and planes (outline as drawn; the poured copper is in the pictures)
AVDD0V8_MIPI on TOP: 13.84,40.77 13.97,40.64 13.97,38.99 13.84,38.86 7.24,38.86 7.11,38.99 7.11,40.64 7.24,40.77
AVDD0V8_MIPI on BOTTOM: 25.91,85.6 26.04,85.47 26.04,84.84 25.91,84.71 21.46,84.71 18.8,82.04 18.8,72.9 14.48,68.58 14.48,57.91 9.65,53.09 9.65,38.99 9.53,38.86 6.99,38.86 6.86,38.99 6.86,57.15 10.79,61.09 10.79,69.47 17.14,75.82 17.14,82.68 20.07,85.6
AVDD0V8_PLL on BOTTOM: 54.74,66.67 54.74,65.66 54.61,65.53 51.56,65.53 51.44,65.66 51.44,67.44 51.56,67.56 53.85,67.56
AVDD1V8_MIPI on TOP: 29.59,60.07 29.72,59.94 29.72,58.93 28.57,57.78 26.8,57.78 26.42,57.4 25.4,57.4 25.27,57.53 25.27,63.37 25.4,63.5 27.18,63.5 27.3,63.37 27.3,60.2 27.43,60.07
AVDD1V8_MIPI on BOTTOM: 26.8,82.68 27.18,83.06 29.46,83.06 29.59,82.93 29.59,82.3 29.08,81.79 27.05,81.79 26.67,81.41 25.65,81.41 25.4,81.15 25.4,76.58 26.29,75.69 26.29,65.79 27.3,64.77 27.3,61.85 27.18,61.72 24.26,61.72 24.13,61.85 24.13,82.55 24.26,82.68
GND on TOP (solid shape): 67.56,40.77 67.56,39.88 67.56,38.99 67.44,38.86 63.25,38.86 63.12,38.99 63.12,40.77 63.25,40.89 67.44,40.89
GND on TOP (solid shape): 14.35,55.5 14.35,53.72 14.22,53.59 13.59,53.59 13.46,53.72 13.46,54.48 13.34,54.61 12.83,54.61 12.7,54.74 12.7,55.5 12.83,55.63 14.22,55.63
GND on TOP (solid shape): 43.94,34.04 43.94,32.26 43.81,32.13 43.18,32.13 43.05,32.26 43.05,33.02 42.93,33.15 42.42,33.15 42.29,33.27 42.29,34.04 42.42,34.16 43.81,34.16
GND on TOP (solid shape): 55.37,90.55 55.37,87.76 55.24,87.63 52.96,87.63 52.83,87.76 52.83,90.55 52.96,90.68 55.24,90.68
GND on TOP (solid shape): 70.36,36.58 70.36,26.42 70.23,26.29 68.58,26.29 68.45,26.42 68.45,26.8 68.45,26.8 68.45,28.58 68.45,28.58 68.45,28.96 68.07,29.34 68.07,30.23 68.07,32.38 67.94,32.51 64.9,32.51 64.77,32.64 64.77,33.4 64.9,33.53 67.94,33.53 68.07,33.66 68.07,35.56 68.07,36.58 68.2,36.7 70.23,36.7
GND on TOP (solid shape): 56.01,40.89 56.01,38.48 55.88,38.35 54.99,38.35 53.97,38.35 53.85,38.35 53.47,38.73 50.8,38.74 50.16,38.73 50.04,38.61 50.04,29.34 49.53,28.83 49.53,24.38 48.39,23.24 46.86,23.24 46.74,23.37 46.74,25.02 46.61,25.15 46.61,26.16 46.61,26.16 46.61,27.69 46.86,27.94 46.86,29.21 46.74,29.34 44.2,29.34 44.07,29.46 44.07,30.23 44.2,30.35 47.37,30.35 47.5,30.48 47.5,36.32 47.5,37.34 47.5,37.59 47.5,38.61 47.5,40.89 47.62,41.02 55.88,41.02
GND on TOP: 51.31,62.36 51.18,62.23 48.64,62.23 48.51,62.36 48.51,64.01 48.64,64.14 51.18,64.14 51.31,64.01
GND on TOP: 61.47,46.99 61.72,47.24 62.74,47.24 62.99,47.5 63.12,47.5 63.25,47.37 63.25,45.72 63.12,45.59 63.12,42.16 62.99,42.04 57.53,42.04 57.4,42.16 57.4,48.39 57.02,48.77 57.02,56.52 58.04,57.53 58.93,57.53 59.05,57.4 59.05,53.85 59.56,53.34 59.56,48.39 59.44,48.26 59.44,47.12 59.56,46.99
GND on TOP: 74.55,81.92 77.85,81.92 77.98,81.79 77.98,79.88 77.85,79.76 74.55,79.76 74.42,79.88 74.42,81.79
GND on TOP: 66.04,62.36 66.55,62.87 66.55,66.67 66.42,66.8 63.88,66.8 63.75,66.93 63.75,67.69 63.88,67.82 66.55,67.82 66.67,67.94 66.67,72.52 67.31,73.15 67.31,75.44 67.06,75.69 67.06,78.61 67.18,78.74 69.98,78.74 70.1,78.61 70.1,76.96 69.53,76.39 69.53,72.33 68.71,71.5 68.71,62.74 68.83,62.61 70.74,62.61 70.87,62.48 70.87,60.58 70.74,60.45 69.6,60.45 69.09,59.94 66.17,59.94 66.04,60.07
GND on TOP: 58.93,33.66 61.72,33.66 61.85,33.53 61.85,32 61.72,31.88 58.93,31.88 58.8,32 58.8,33.53
GND on TOP: 12.95,41.4 12.83,41.27 9.14,41.27 9.02,41.4 9.02,43.69 9.14,43.81 12.57,43.81 12.95,43.43
GND on TOP: 24,20.57 23.24,20.57 23.11,20.7 23.11,23.37 22.99,23.5 17.65,23.5 17.02,24.13 14.73,24.13 14.48,23.88 11.18,23.88 11.05,24 11.05,25.53 11.18,25.65 30.48,25.65 30.61,25.53 30.61,23.24 30.48,23.11 25.78,23.11 25.53,23.37 24.26,23.37 24.13,23.24 24.13,20.7
GND on TOP: 62.1,127.13 62.23,127 62.23,125.09 62.1,124.97 57.66,124.97 57.53,125.09 57.53,127 57.66,127.13
GND on TOP: 54.99,26.54 54.99,28.07 55.12,28.19 56.64,28.19 56.77,28.07 56.77,26.54 56.64,26.42 55.12,26.42
GND on TOP: 40.64,57.15 40.51,57.28 40.51,57.66 40.39,57.78 37.08,57.78 36.96,57.91 36.96,59.94 37.08,60.07 42.67,60.07 42.8,59.94 42.8,57.28 42.67,57.15
GND on TOP: 38.1,25.4 37.97,25.53 37.97,29.46 37.85,29.59 33.78,29.59 32.77,28.57 30.48,28.57 30.35,28.7 30.35,32.38 30.23,32.51 24.89,32.51 24.77,32.38 24.77,29.59 24.64,29.46 23.75,29.46 23.62,29.59 23.62,32.38 23.5,32.51 19.68,32.51 19.56,32.38 19.56,29.59 19.43,29.46 16.76,29.46 16.64,29.59 16.64,32.38 16.51,32.51 13.84,32.51 13.72,32.64 13.72,33.4 13.84,33.53 16.51,33.53 16.64,33.66 16.64,37.21 16.76,37.34 19.18,37.34 19.3,37.21 19.3,33.66 19.43,33.53 23.37,33.53 23.5,33.66 23.5,37.21 23.62,37.34 24.64,37.34 24.77,37.21 24.77,33.66 24.89,33.53 30.23,33.53 30.35,33.66 30.35,37.21 30.48,37.34 32.51,37.34 32.64,37.21 32.64,32.89 34.16,31.37 37.85,31.37 37.97,31.5 37.97,35.43 38.1,35.56 38.99,35.56 39.12,35.43 39.12,25.53 38.99,25.4
GND on TOP: 36.07,10.54 36.2,10.41 36.2,9.14 36.07,9.02 33.53,9.02 33.4,9.14 33.4,10.41 33.53,10.54
GND on TOP: 67.06,80.9 67.18,80.77 67.18,79.88 67.06,79.76 63.25,79.76 63.12,79.88 63.12,80.77 63.25,80.9
GND on TOP: 59.94,106.55 59.94,109.22 60.07,109.35 64.52,109.35 64.64,109.22 64.64,106.55 64.52,106.43 60.07,106.43
GND on TOP: 77.47,94.74 77.34,94.61 74.04,94.61 73.91,94.74 73.91,97.54 74.04,97.66 77.34,97.66 77.47,97.54
GND on TOP: 71.37,101.22 73.66,101.22 74.17,100.71 74.17,99.44 73.91,99.19 71.37,99.19 71.25,99.31 71.25,101.09
GND on TOP: 35.31,40.89 35.31,39.24 35.18,39.12 33.15,39.12 33.02,39.24 33.02,40.89 33.15,41.02 35.18,41.02
GND on TOP: 59.82,13.08 60.07,12.83 60.07,8.64 58.42,6.99 45.47,6.99 45.34,7.11 45.34,12.95 45.47,13.08
GND on TOP: 10.92,60.45 10.79,60.33 6.86,60.33 6.73,60.45 6.73,63.88 6.86,64.01 10.79,64.01 10.92,63.88
GND on TOP: 72.52,109.09 74.04,109.09 74.42,108.71 74.42,107.95 73.61,107.14 71.81,107.14 71.63,107.31 71.63,108.2
GND on TOP: 71.63,11.05 72.9,11.05 73.53,10.41 74.42,10.41 74.55,10.29 74.55,8.26 74.42,8.13 71.63,8.13 71.5,8.26 71.5,10.92
GND on TOP: 50.8,77.09 50.8,78.87 50.93,78.99 52.96,78.99 53.09,79.12 53.09,80.64 53.21,80.77 54.48,80.77 54.61,80.64 54.61,79.25 54.74,79.12 56.13,79.12 56.52,79.5 56.52,81.41 56.39,81.53 54.99,81.53 54.86,81.66 54.86,83.44 54.74,83.57 51.69,83.57 51.56,83.69 51.56,84.07 51.69,84.2 57.15,84.2 57.28,84.07 57.28,79.38 56.13,78.23 53.21,78.23 53.09,78.11 53.09,77.09 52.96,76.96 50.93,76.96
GND on TOP: 60.33,67.18 60.45,67.06 60.45,66.29 60.33,66.17 57.02,66.17 56.52,65.66 54.99,65.66 54.86,65.79 54.86,67.44 55.12,67.69 56.13,67.69 56.64,67.18
GND on TOP: 35.05,60.71 34.92,60.58 27.69,60.58 27.56,60.71 27.56,63.37 27.69,63.5 34.92,63.5 35.05,63.37
GND on TOP: 74.17,70.23 74.42,69.98 74.42,68.45 74.3,68.33 71.37,68.33 71.25,68.45 71.25,70.1 71.37,70.23
GND on TOP: 17.27,44.58 17.14,44.7 17.14,46.48 17.02,46.61 17.02,49.15 17.27,49.4 17.27,50.67 17.14,50.8 14.61,50.8 14.48,50.93 14.48,51.69 14.61,51.82 17.78,51.82 17.91,51.94 17.91,61.85 18.03,61.98 19.81,61.98 19.94,61.85 19.94,60.2 20.07,60.07 22.23,60.07 22.35,59.94 22.35,52.96 22.23,52.83 20.07,52.83 19.94,52.7 19.94,44.7 19.81,44.58
GND on TOP: 51.05,22.35 52.96,22.35 53.09,22.48 55.37,22.48 55.5,22.35 55.5,21.08 55.37,20.95 49.28,20.95 49.15,21.08 49.15,22.61 49.28,22.73 50.67,22.73
GND on TOP: 3.68,87.88 6.73,87.88 6.86,87.76 6.86,84.2 6.73,84.07 3.68,84.07 3.56,84.2 3.56,87.76
GND on TOP: 22.86,41.02 22.86,39.12 22.73,38.99 20.07,38.99 19.94,39.12 19.94,41.02 20.07,41.15 22.73,41.15
GND on TOP: 19.43,15.75 19.43,19.81 19.56,19.94 21.21,19.94 21.34,19.81 21.34,15.75 21.21,15.62 19.56,15.62
GND on TOP: 30.48,65.41 30.35,65.53 30.35,68.58 30.48,68.71 32.89,68.71 33.02,68.58 33.02,65.53 32.89,65.41
GND on TOP: 53.21,87.12 53.21,85.98 53.09,85.85 50.8,85.85 50.67,85.98 50.67,87 50.93,87.25 53.09,87.25
GND on TOP: 55.24,62.74 55.37,62.87 57.53,62.87 57.66,62.74 57.66,60.33 57.53,60.2 55.37,60.2 55.24,60.33
GND on TOP: 35.43,22.35 35.56,22.23 35.56,19.56 35.43,19.43 31.75,19.43 31.62,19.56 31.62,22.23 31.75,22.35
GND on TOP: 66.8,139.32 69.85,139.32 69.98,139.19 69.98,137.41 69.85,137.29 66.8,137.29 66.67,137.41 66.67,139.19
GND on TOP: 71.88,76.33 73.53,76.33 74.55,77.34 74.55,78.23 74.42,78.36 71.5,78.36 71.37,78.23 71.37,76.83
GND on TOP: 64.39,96.27 67.56,96.27 67.69,96.14 67.69,92.84 67.56,92.71 64.39,92.71 64.26,92.84 64.26,96.14
GND on TOP: 24.77,42.93 24.77,46.99 24.64,47.12 21.97,47.12 21.84,47.24 21.84,48.01 21.97,48.13 24.64,48.13 24.77,48.26 24.77,51.82 24.89,51.94 27.69,51.94 27.81,51.82 27.81,49.78 29.46,48.13 32.13,48.13 32.26,48.26 32.26,53.59 32.38,53.72 33.53,53.72 35.31,51.94 35.31,48.51 35.43,48.39 42.55,48.39 42.8,48.13 45.34,48.13 45.47,48.26 45.47,51.82 45.59,51.94 46.99,51.94 47.12,52.07 47.12,58.17 47.62,58.67 48.13,58.67 48.26,58.55 48.26,53.98 48.64,53.59 48.64,48.13 48.77,48.01 50.67,48.01 50.93,48.26 51.94,48.26 52.2,48.51 52.32,48.51 52.45,48.39 52.45,46.74 52.32,46.61 52.32,43.18 52.2,43.05 45.59,43.05 45.47,43.18 45.47,46.99 45.34,47.12 42.67,47.12 42.42,46.86 35.43,46.86 35.31,46.74 35.31,44.83 34.92,44.45 34.92,43.05 34.8,42.93 32.51,42.93 32.38,43.05 32.38,46.99 32.26,47.12 29.21,47.12 27.05,44.96 27.05,44.07 26.67,43.69 26.67,42.93 26.54,42.8 24.89,42.8
GND on TOP: 6.86,106.68 6.86,103 6.73,102.87 4.45,102.87 4.32,103 4.32,106.68 4.45,106.81 6.73,106.81
GND on TOP: 71.25,19.56 74.17,19.56 74.42,19.3 74.42,18.03 73.28,16.89 71.25,16.89 71.12,17.02 71.12,19.43
GND on TOP: 29.72,38.99 29.59,38.86 26.67,38.86 26.54,38.99 26.54,40.89 26.67,41.02 29.59,41.02 29.72,40.89
GND on BOTTOM: 63.75,65.53 63.75,67.69 63.88,67.82 68.58,67.82 68.71,67.69 68.71,65.53 68.58,65.41 63.88,65.41
GND on BOTTOM: 39.37,65.15 39.24,65.02 37.08,65.02 36.96,65.15 36.96,67.44 37.08,67.56 39.24,67.56 39.37,67.44
GND on BOTTOM: 26.8,68.71 31.24,68.71 31.37,68.58 31.37,67.06 31.11,66.8 31.11,65.66 30.99,65.53 27.43,65.53 26.67,66.29 26.67,68.58
GND on BOTTOM: 38.86,87.12 38.73,87 37.97,87 37.85,87.12 37.85,92.08 39.75,93.98 40.39,93.98 40.51,93.85 40.51,92.96 38.86,91.31
GND on BOTTOM: 26.16,137.67 26.29,137.54 26.29,134.49 26.16,134.37 23.11,134.37 22.99,134.49 22.99,137.54 23.11,137.67
GND on BOTTOM: 40.77,71.5 40.64,71.63 40.64,76.96 40.77,77.09 43.81,77.09 43.94,76.96 43.94,71.63 43.81,71.5
GND on BOTTOM: 57.66,124.97 57.53,125.09 57.53,127 57.66,127.13 61.34,127.13 62.23,126.24 62.23,125.09 62.1,124.97
GND on BOTTOM: 36.7,78.99 36.83,79.12 37.72,79.12 38.1,78.74 38.1,74.42 37.97,74.3 36.83,74.3 36.7,74.42
GND on BOTTOM: 55.37,87.76 55.24,87.63 52.96,87.63 52.83,87.76 52.83,90.55 52.96,90.68 55.24,90.68 55.37,90.55
GND on BOTTOM: 43.43,89.41 43.56,89.28 43.56,87.5 43.43,87.38 40.77,87.38 40.64,87.5 40.64,89.28 40.77,89.41
GND on BOTTOM: 8.38,137.41 10.29,137.41 10.41,137.29 10.41,133.86 10.29,133.73 8.38,133.73 8.26,133.86 8.26,137.29
GND on BOTTOM: 33.53,89.03 33.66,88.9 33.66,84.96 33.53,84.84 30.23,84.84 30.1,84.96 30.1,85.34 29.97,85.47 27.05,85.47 26.29,86.23 24.38,86.23 24.26,86.36 24.26,90.17 24.51,90.42 27.43,90.42 27.56,90.3 27.56,89.15 27.69,89.03
GND on BOTTOM: 52.07,14.99 52.45,14.61 61.98,14.61 62.36,14.22 62.36,12.19 62.23,12.06 54.61,12.06 53.34,10.79 52.32,10.79 52.2,10.67 52.2,7.24 52.07,7.11 45.09,7.11 44.96,7.24 44.96,14.86 45.09,14.99
GND on BOTTOM: 11.94,111.76 11.94,108.97 11.81,108.84 11.05,108.84 10.92,108.97 10.92,111.76 10.29,112.39 10.29,114.17 10.41,114.3 12.45,114.3 12.57,114.17 12.57,112.39
GND on BOTTOM: 26.67,83.06 26.16,83.06 25.91,83.31 22.35,83.31 22.23,83.44 22.23,84.33 22.35,84.45 26.04,84.45 26.8,83.69 26.8,83.19
GND on BOTTOM: 23.88,127 25.91,127 26.04,126.87 26.04,122.17 25.91,122.05 23.88,122.05 23.75,122.17 23.75,126.87
GND on BOTTOM: 19.3,80.52 21.34,80.52 21.46,80.39 21.46,71.37 21.34,71.25 19.3,71.25 19.18,71.37 19.18,80.39
GND on BOTTOM: 10.29,127.13 10.41,127 10.41,124.21 10.29,124.08 8.76,124.08 8.64,124.21 8.64,126.36 9.4,127.13
GND on BOTTOM: 67.06,85.72 68.2,85.72 68.58,86.11 70.61,86.11 70.74,85.98 70.74,84.45 70.61,84.33 67.06,84.33 66.93,84.45 66.93,85.6
GND on BOTTOM: 54.74,65.02 54.86,64.9 54.86,63.25 54.74,63.12 52.32,63.12 52.2,63.25 52.2,64.9 52.32,65.02
GND on GND02, GND05: 2,0.64 1.03,1.03 0.64,2 0.64,138 1.03,138.96 2,139.36 78.07,139.36 79.03,138.96 79.43,138 79.43,2 79.03,1.03 78.07,0.64
GND on ART03: 72.52,98.93 71.88,99.57 71.88,114.3 70.99,115.19 57.91,115.19 57.66,114.94 57.66,108.97 57.53,108.84 55.75,108.84 55.63,108.97 55.63,123.19 59.94,127.51 61.34,127.51 62.23,128.4 62.23,139.36 78.07,139.36 79.03,138.96 79.43,138 79.43,99.19 79.18,98.93
GND on ART03: 0.64,138 1.03,138.96 2,139.36 10.5,139.36 11.05,138.81 11.05,134.37 5.33,128.65 5.33,107.82 5.08,107.57 0.76,107.57 0.64,107.7 0.64,110.11
GND on POWER04: 2,0.64 1.03,1.03 0.64,2 0.64,6.1 1.02,6.48 5.08,6.48 6.86,4.7 72.52,4.7 76.33,8.51 76.33,40.26 76.45,40.39 79.31,40.39 79.43,40.26 79.43,2 79.03,1.03 78.07,0.64
GND on POWER04: 75.44,133.35 72.14,136.65 7.37,136.65 6.99,136.27 6.99,110.36 6.86,110.24 0.76,110.24 0.64,110.36 0.64,138 1.03,138.96 2,139.36 78.07,139.36 79.03,138.96 79.43,138 79.43,78.93 78.99,78.49 75.82,78.49 75.44,78.87
VBUS on TOP: 69.34,16.64 73.15,16.64 73.28,16.51 73.28,16.26 73.15,16.13 71.5,16.13 71.37,16 71.37,11.94 71.5,11.81 73.15,11.81 73.28,11.68 73.28,11.3 73.15,11.18 71.37,11.18 71.25,11.05 71.25,8.64 71.12,8.51 69.34,8.51 69.22,8.64 69.22,16.51
VBUS_CHARGE on TOP: 33.66,11.18 33.53,11.3 33.53,13.97 33.66,14.1 35.69,14.1 35.81,13.97 35.81,11.3 35.69,11.18
VBUS_CHARGE on BOTTOM: 33.4,13.84 41.53,13.84 41.78,13.59 41.78,8.51 41.66,8.38 33.4,8.38 33.27,8.51 33.27,13.72
VBUS_IN on TOP: 66.42,112.9 66.29,113.03 66.29,115.32 66.42,115.44 71.63,115.44 71.75,115.32 71.75,113.03 71.63,112.9
VBUS_IN on TOP: 68.33,15.24 68.07,14.99 46.1,14.99 43.94,12.83 38.86,12.83 38.73,12.95 38.73,19.68 38.99,19.94 68.2,19.94 68.33,19.81
VBUS_IN on BOTTOM: 62.36,16 52.32,16 51.82,15.49 49.53,15.49 49.4,15.62 49.4,19.68 49.53,19.81 62.48,19.81 62.61,19.68 62.61,16.26
VDD0V8_CPU on TOP (solid shape): 40.64,36.45 40.64,35.69 40.77,35.56 41.4,35.56 41.53,35.43 41.53,32.26 41.4,32.13 39.62,32.13 39.5,32.26 39.5,36.45 39.62,36.58 40.51,36.58
VDD0V8_CPU on TOP: 50.93,65.53 48.64,65.53 48.51,65.66 48.51,67.56 48.64,67.69 50.93,67.69 51.05,67.56 51.05,65.66
VDD0V8_CPU on TOP: 57.4,59.69 57.53,59.56 57.53,57.78 56.64,56.9 54.23,56.9 54.1,57.02 54.1,59.56 54.23,59.69
VDD0V8_CPU on BOTTOM: 40.13,75.95 40.13,71.63 40.01,71.5 37.72,71.5 37.59,71.63 37.59,73.41 38.61,74.42 38.61,75.95 38.73,76.07 40.01,76.07
VDD0V8_CPU on BOTTOM: 50.55,47.62 56.9,53.98 56.9,59.05 56.77,59.18 48.01,59.18 40.01,51.18 40.01,31.88 40.13,31.75 50.42,31.75 50.55,31.88
VDD0V8_CPU on POWER04: 34.42,79.88 34.09,79.55 32.46,79.55 32.33,79.43 32.33,79.1 32.77,78.66 32.77,76.63 39.88,69.52 39.88,56.26 40.13,56.01 56.77,56.01 57.02,56.26 57.02,63.25 40.39,79.88
VDD0V8_DDR_CORE on ART03 (solid shape): outline of 1549 points within 21.15,61.34 33.02,79.12
VDD0V8_DDR_CORE on TOP: 23.88,63.5 24,63.37 24,60.71 23.88,60.58 20.45,60.58 20.32,60.71 20.32,63.37 20.45,63.5
VDD0V8_DDR_CORE on BOTTOM: 28.83,70.61 28.83,69.34 28.7,69.22 26.8,69.22 26.67,69.34 26.67,70.61 26.8,70.74 28.7,70.74
VDD0V8_KPU on TOP: 68.45,59.31 68.58,59.18 68.58,56.01 67.94,55.37 65.53,55.37 63.75,57.15 63.75,59.18 63.88,59.31
VDD0V8_KPU on TOP: 51.44,88.27 51.31,88.14 48.01,88.14 47.88,88.27 47.88,89.53 49.15,90.81 51.31,90.81 51.44,90.68
VDD0V8_KPU on TOP: 58.8,37.34 58.93,37.47 62.87,37.47 62.99,37.34 62.99,34.29 62.87,34.16 58.93,34.16 58.8,34.29
VDD0V8_KPU on BOTTOM: 51.44,88.27 51.31,88.14 48.01,88.14 47.88,88.27 47.88,89.53 49.15,90.81 51.31,90.81 51.44,90.68
VDD0V8_KPU on BOTTOM: 35.69,87.12 35.69,89.66 36.32,90.3 36.32,91.31 36.45,91.44 37.21,91.44 37.34,91.31 37.34,87.12 37.21,87 35.81,87
VDD0V8_KPU on ART03: 61.09,39.88 61.09,54.36 62.23,55.5 62.23,58.29 62.36,58.42 69.47,58.42 69.72,58.17 69.72,45.59 69.34,45.21 69.34,34.29 69.22,34.16 59.94,34.16 59.82,34.29 59.82,38.61
VDD0V8_KPU on POWER04: 32.26,81.28 32.26,92.2 32.64,92.58 49.4,92.58 64.9,77.09 70.1,77.09 70.36,76.83 70.36,57.4 68.96,56.01 58.04,56.01 57.78,56.26 57.78,63.5 40.89,80.39 34.8,80.39 34.04,81.15 32.38,81.15
VDD1V1_DDR on TOP: 35.81,63.5 39.12,63.5 40.01,62.61 40.01,60.71 39.88,60.58 35.81,60.58 35.69,60.71 35.69,63.37
VDD1V1_DDR on TOP: 36.58,38.61 36.7,38.48 36.7,37.47 35.31,36.07 33.15,36.07 33.02,36.2 33.02,38.48 33.15,38.61
VDD1V1_DDR on BOTTOM: 38.23,45.34 39.24,46.35 39.24,51.44 43.69,55.88 43.69,63.37 43.56,63.5 36.96,63.5 36.83,63.37 36.83,57.66 33.02,53.85 33.02,36.2 33.15,36.07 38.1,36.07 38.23,36.2
VDD1V1_DDR on BOTTOM: 31.37,70.61 31.37,69.34 31.24,69.22 29.21,69.22 29.08,69.34 29.08,70.61 29.21,70.74 31.24,70.74
VDD1V1_DDR on POWER04: 31.37,78.49 31.8,78.92 32.11,78.92 32.38,78.64 32.38,76.52 39.12,69.79 39.12,56.13 38.99,56.01 26.54,56.01 26.29,56.26 26.29,75.95 28.83,78.49
VDD1V1_DDR_DRAM on TOP: 38.73,64.52 33.66,64.52 33.53,64.64 33.53,68.96 33.4,69.09 28.83,69.09 28.7,69.22 28.7,72.77 29.08,73.15 29.08,74.68 29.21,74.8 29.46,74.8 29.59,74.68 29.59,73.15 29.72,73.03 30.23,73.03 32,74.8 33.27,74.8 42.55,65.53 42.55,64.52 44.07,62.99 44.07,60.83 43.94,60.71 40.77,60.71 40.64,60.83 40.64,62.61
VDD1V8_DDR_VDD1 on TOP: 23.5,37.85 23.37,37.97 23.37,41.02 23.5,41.15 25.15,41.15 25.27,41.02 25.27,37.97 25.15,37.85
VDD1V8_DDR_VDD1 on TOP: 32.26,57.53 32.13,57.4 29.59,57.4 29.46,57.53 29.46,58.17 29.97,58.67 29.97,59.94 30.1,60.07 32.13,60.07 32.26,59.94
VDD1V8_DDR_VDD1 on BOTTOM: 27.81,38.48 27.69,38.35 24.51,38.35 24.38,38.48 24.38,58.04 28.19,61.85 28.19,64.39 28.7,64.9 31.24,64.9 31.62,65.28 31.62,69.98 31.75,70.1 33.91,70.1 34.04,69.98 34.04,64.64 33.66,64.26 33.66,60.33 27.81,54.48
VDD_0V8 on TOP (solid shape): 10.92,58.8 10.92,57.28 11.18,57.02 11.81,57.02 11.94,56.9 11.94,53.85 11.81,53.72 6.86,53.72 6.73,53.85 6.73,58.8 6.86,58.93 10.79,58.93
VDD_0V8 on BOTTOM: 23.62,71.25 22.1,71.25 21.97,71.37 21.97,80.39 22.1,80.52 23.62,80.52 23.75,80.39 23.75,71.37
VDD_0V8 on POWER04: 32.26,80.9 33.99,80.9 34.09,80.8 34.09,80.06 33.86,79.83 32.33,79.83 31.37,78.87 28.7,78.87 25.4,75.56 25.4,49.78 24.89,49.28 8.89,49.28 8.76,49.4 8.76,83.44 13.72,88.39 31.5,88.39 31.75,88.14 31.75,81.41
VDD_1V8 on TOP: 35.94,44.96 35.94,46.48 36.07,46.61 36.96,46.61 37.08,46.48 37.08,44.7 37.47,44.32 37.47,42.67 37.34,42.55 35.56,42.55 35.43,42.67 35.43,44.45
VDD_1V8 on TOP: 36.32,29.21 36.45,29.34 37.34,29.34 37.47,29.21 37.47,25.53 37.34,25.4 35.69,25.4 35.56,25.53 35.56,27.05 36.32,27.81
VDD_1V8 on TOP: 22.99,43.43 22.99,45.85 23.37,46.23 23.37,46.74 23.5,46.86 24,46.86 24.13,46.74 24.13,43.43 24,43.31 23.11,43.31
VDD_1V8 on TOP: 55.24,68.33 55.12,68.45 55.12,69.22 55.88,69.98 55.88,74.55 57.78,76.45 57.78,78.49 58.04,78.74 60.07,78.74 60.2,78.61 60.2,75.69 60.83,75.06 60.83,73.79 60.71,73.66 59.05,73.66 58.93,73.79 58.93,74.68 58.8,74.8 57.4,74.8 57.15,74.55 57.15,69.98 57.4,69.72 57.78,69.72 57.91,69.6 57.91,68.58 57.66,68.33 57.66,67.56 57.53,67.44 56.77,67.44 56.39,67.82 56.39,68.2 56.26,68.33
VDD_1V8 on BOTTOM: 62.23,80.14 63.12,81.03 71.12,81.03 71.25,80.9 71.25,77.09 71.12,76.96 57.91,76.96 57.78,77.09 57.78,80.01 57.91,80.14
VDD_1V8 on BOTTOM: 29.84,89.28 28.45,89.28 28.32,89.41 28.32,90.3 28.45,90.42 29.84,90.42 29.97,90.3 29.97,89.41
VDD_1V8 on ART03: 27.69,78.49 28.57,78.49 29.59,79.5 33.02,79.5 33.91,78.61 36.83,78.61 43.69,85.47 43.69,91.19 42.42,92.46 42.42,96.27 42.16,96.52 39.24,96.52 38.99,96.27 38.99,94.49 37.21,92.71 37.21,86.11 34.23,83.12 33.72,83.12 33.15,83.69 29.59,83.69 28.19,82.3 28.19,80.52 27.56,79.88 27.56,78.61
